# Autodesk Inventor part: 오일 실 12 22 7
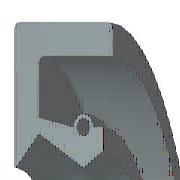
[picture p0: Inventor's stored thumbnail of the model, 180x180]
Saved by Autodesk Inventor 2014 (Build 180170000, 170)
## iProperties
Created: 2012-02
Part Number: 오일 실 12 22 7
Material: 고무
Description: 오일-실
Document SubType Name: Modeling
Standard: KS B 2804
Designer: mduedu
Standards Organization: KS
Language: ko-KR
Size Designation: D - 12 22 7
Categories: <MemberInstance><Categories><Category DisplayName="샤프트 부품" InternalName="7f7aeb1f-a693-4053-b835-cee3144e0d98" Mnemonic="SHFT"><Category DisplayName="실링" Intern
Density: 0.93 g/cm^3
Mass: 1.25383 g
Surface Area: 18.4996 cm^2
Volume: 1.3482 cm^3
Appearance: 고무 - 검은색 - 버전 1.1
IsCustomPart: 1
Author: mduedu
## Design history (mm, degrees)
revolve "본체" stored, may be unused: angle "d17" = 90 deg
revolve "스프링1" stored, may be unused: angle "d18" = 90 deg
body "Solid1"
sketch "스케치1"
  geometry: L1 (0, 11)-(7, 11); L2 (7, 9.25)-(1.75, 9.25); L3 (1.75, 7.75)-(4.9, 6); L4 (4.9, 6)-(0, 6); L5 (0, 0)-(9.586, 0) reference; L6 (4.9, 6)-(6.3, 6.875); L7 (0, 18)-(0, -3) reference; L8 (-1.941, 0)-(11.507, 0) reference; L9 (4.2, 8.1)-(1.75, 8.59); L10 (1.75, 8.59)-(1.75, 9.25); L11 (0, 11)-(0, 6.088); L12 (4.9, 6)-(0, 6); L13 (1.75, 7.75)-(0.152, 6.028); L14 (7, 11)-(7, 9.25); L15 (5.6, 8.1)-(6.3, 8.1); L16 (6.3, 8.1)-(6.3, 6.875); C1 r 0.455 at (4.9, 8.1); A1 r 0.7 centre (4.9, 8.1) between (5.6, 8.1) and (4.2, 8.1); A2 r 0.088 centre (0.088, 6.088) between (0, 6.088) and (0.152, 6.028); 1 further point
  constraints: 28 end point, 5 horizontal alignment, 5 point on line, 4 point on circle, 4 vertical alignment, 3 centre point, 3 tangent, 2 collinear, 2 horizontal, 2 perpendicular, 1 coincident, 1 parallel
  dimensions: "d0" = 22 diameter of L1 L5 (= SD2); "d1" = 1.75 distance of L1.end L2.start (= SD); "d2" = 0.91 diameter of C1 (= SPDI); "d3" = 1.4 diameter of A1 (= SPDA); "d4" = 12 diameter of L3.end L5 (= NND); "d5" = 15.5 diameter of L3.start L5 (= TKDM); "d7" = 17.18 diameter of L9.end L5 (= TKDM + 0.24 x SWDT); "d8" = 1.75 distance between parallel lines of L11 L10 (= SD); "d9" = 4.9 distance from line of L11 C1.centre (= SPDST); "d10" = 16.2 diameter of C1.centre L5 (= HLDM); "d11" = 0.0875 radius of A2 (= 0.25 x LAB); "d12" = 6.3 distance between parallel lines of L11 L16 (= SDI); "d13" = 13.75 diameter of L6.end L5 (= ABDM); "d14" = 7 distance from line of L11 L1.end (= SWDT)
fillet "모깎기1" dims "d6" = 0.3 (= RR)
other parameters: "SD2" = 22 [user parameter; used in 1 equation term], "SWDT" = 7 [user parameter; used in 2 equation terms], "RR" = 0.3 [user parameter; used in 1 equation term], "SD" = 1.75 [user parameter; used in 2 equation terms], "NND" = 12 [user parameter; used in 1 equation term], "SPDA" = 1.4 [user parameter; used in 1 equation term], "SPDI" = 0.91 [user parameter; used in 1 equation term], "TKDM" = 15.5 [user parameter; used in 2 equation terms], "HLDM" = 16.2 [user parameter; used in 1 equation term], "ABDM" = 13.75 [user parameter; used in 1 equation term], "SDI" = 6.3 [user parameter; used in 1 equation term], "SPDST" = 4.9 [user parameter; used in 1 equation term], "LAB" = 0.35 [user parameter; used in 1 equation term], "d15" = 0, "d16" = 0, "d19" = 0
